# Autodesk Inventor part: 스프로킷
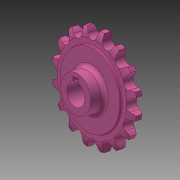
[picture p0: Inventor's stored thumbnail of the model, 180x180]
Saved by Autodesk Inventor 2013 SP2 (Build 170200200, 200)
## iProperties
Created: 2016-03
Part Number: 스프로킷
Material: 강철, 탄소
Document SubType Name: Modeling
Designer: mduedu
Density: 7.87 g/cm^3
Mass: 301.818 g
Surface Area: 124.882 cm^2
Volume: 38.3505 cm^3
Author: mduedu
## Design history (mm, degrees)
sketch "스케치1"
  geometry: L1 (0, 5)-(25, 5); L2 (25, 5)-(25, 4.1); L3 (25.5, 3.6)-(29.125, 3.6); L4 (35.5, 2)-(35.5, 0); L5 (35.5, 0)-(0, 0); L6 (0, 0)-(0, 5); L7 (0, -5)-(25, -5); L8 (25, -5)-(25, -4.1); L9 (25.5, -3.6)-(29.125, -3.6); L10 (35.5, -2)-(35.5, 0); L11 (0, 0)-(0, -5); A1 r 13.5 centre (29.125, -9.9) between (35.5, 2) and (29.125, 3.6); A2 r 13.5 centre (29.125, 9.9) between (29.125, -3.6) and (35.5, -2); A3 r 0.5 centre (25.5, 4.1) between (25, 4.1) and (25.5, 3.6); A4 r 0.5 centre (25.5, -4.1) between (25.5, -3.6) and (25, -4.1); 2 further points
  constraints: 22 end point, 8 point on circle, 6 symmetric about line, 5 tangent, 4 centre point, 4 parallel, 4 point on line, 1 equal radius, 1 horizontal, 1 perpendicular, 1 other
  dimensions: "d0" = 71 diameter of L4 L6; "d2" = 50 diameter of L2 L6; "d3" = 1.6 vertical distance of L4.start L3.end; "d4" = 3.6 distance from line of L4.end L3; "d5" = 5 distance between parallel lines of L5 L1; "d6" = 13.5 radius of A1; "d15" = 0.5 radius of A3
revolve "회전1" sketch "스케치1" stored, may be unused: angle "d7" = 90 deg
sketch "스케치2" dims "d8" = 57.16, "d11" = 71
  geometry: L1 (0, 0)-(0, 28.58); A1 r 32.55 centre (0, 0) between (-16.114, 28.281) and (0, 32.55); A2 r 3.97 centre (0, 32.55) between (-3.838, 31.533) and (0, 28.58); A3 r 12.7 centre (-16.114, 28.281) between (-3.838, 31.533) and (-5.392, 35.088); A4 r 12.7 centre (16.114, 28.281) between (5.392, 35.088) and (3.838, 31.533); A5 r 3.97 centre (0, 32.55) between (0, 28.58) and (3.838, 31.533); A6 r 35.5 centre (0, 0) between (5.392, 35.088) and (-5.392, 35.088); 2 further points
  constraints: 12 point on circle, 6 centre point, 4 coincident, 3 symmetric about line, 2 end point, 1 point on line, 1 tangent, 1 vertical, 1 vertical alignment, 7 other
  dimensions: "d10" = 65.1 diameter of A1; "d12" = 12.7 radius of A3
extrude "돌출1" cut sketch "스케치2" stored distance "d13" = 10; taper "d14" = 0 deg
sketch "스케치3"
  geometry: C1 r 12.5 at (0, 0); 1 further point
  constraints: 1 centre point, 1 coincident
  dimensions: "d19" = 25 diameter of C1
extrude "돌출2" join sketch "스케치3" distance "d20" = 10; taper "d21" = 0 deg
fillet "모깎기1" dims "d22" = 3
sketch "스케치4"
  geometry: L1 (-2.5, 0)-(2.5, 0); L2 (2.5, 0)-(2.5, 9.8); L3 (2.5, 9.8)-(-2.5, 9.8); L4 (-2.5, 9.8)-(-2.5, 0); C1 r 7.5 at (0, 0); 2 further points
  constraints: 8 end point, 2 coincident, 2 parallel, 1 centre point, 1 horizontal, 1 midpoint, 1 perpendicular
  dimensions: "d23" = 15 diameter of C1; "d25" = 5 distance of L2.end L3.end; "d26" = 9.8 distance of L1.end L2.end
extrude "돌출3" cut sketch "스케치4" stored distance "d27" = 8; taper "d28" = 0 deg
node "솔리드1"
pattern_circular "원형 패턴1" dims angle "d17" = 360 deg
